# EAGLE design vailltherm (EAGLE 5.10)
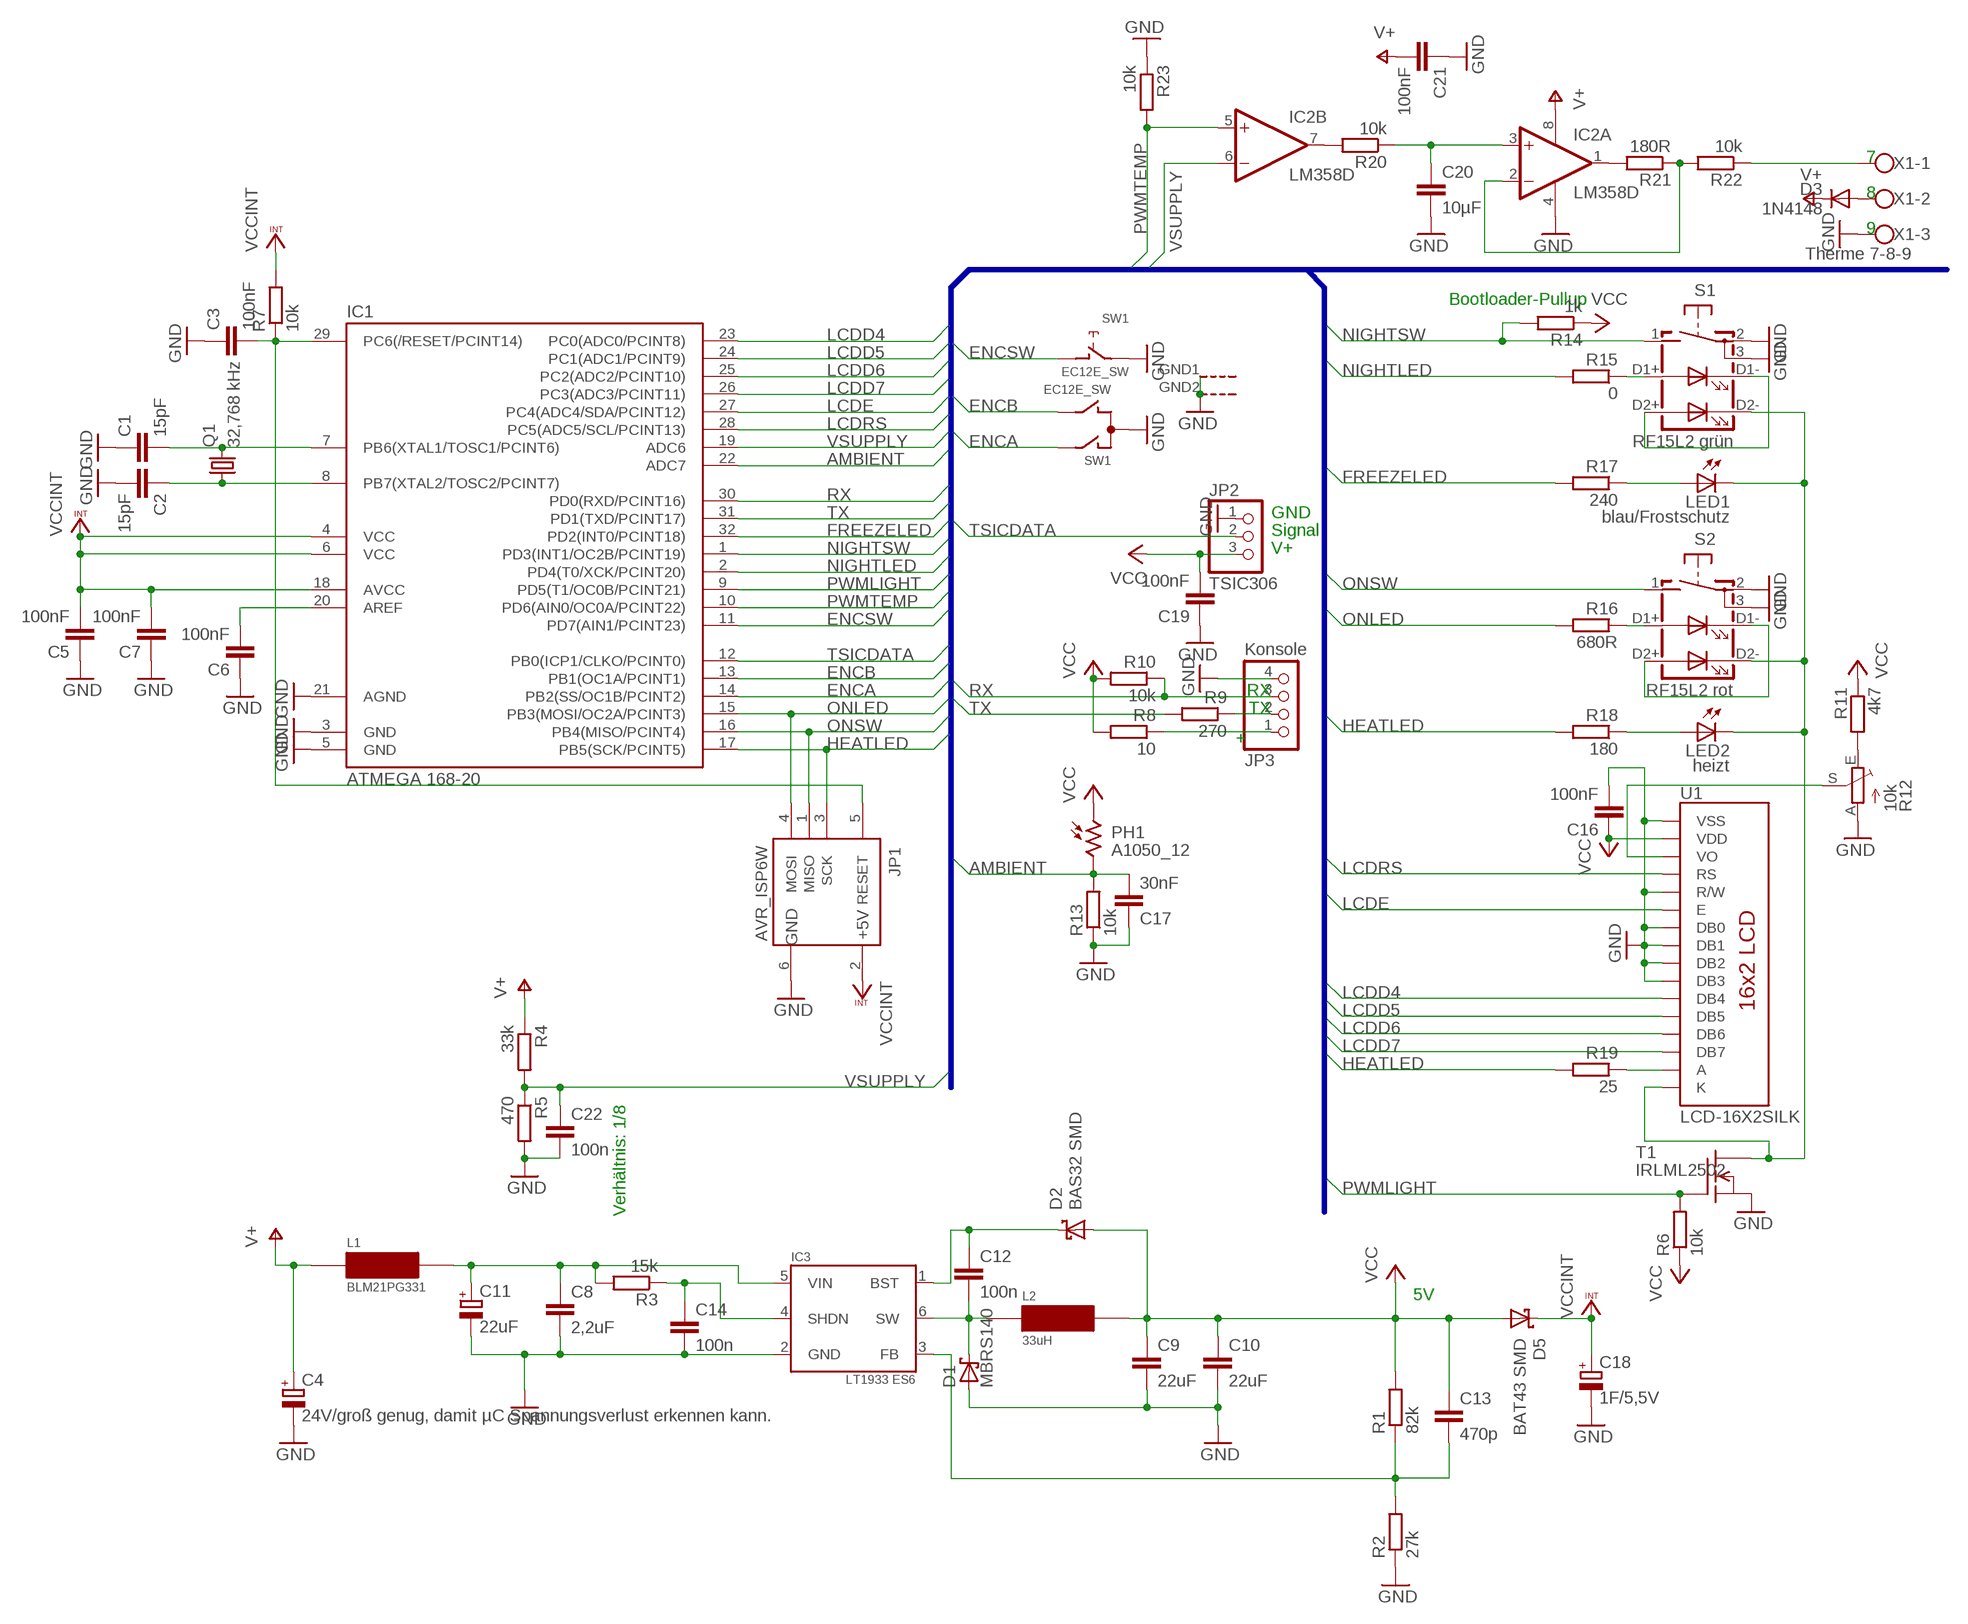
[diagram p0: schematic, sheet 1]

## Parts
C1  15pF  C-EUC0805  [C0805]
C2  15pF  C-EUC0805  [C0805]
C3  100nF  C-EUC0805  [C0805]
C4  24V/groß genug, damit µC Spannungsverlust erkennen kann.  CPOL-EUE5-10.5  [E5-10,5]
C5  100nF  C-EUC0805  [C0805]
C6  100nF  C-EUC0805  [C0805]
C7  100nF  C-EUC0805  [C0805]
C8  2,2uF  C-EUC1206  [C1206]
C9  22uF  C-EUC1206  [C1206]
C10  22uF  C-EUC1206  [C1206]
C11  22uF  CPOL-EUC  [PANASONIC_C]
C12  100n  C-EUC0805  [C0805]
C13  470p  C-EUC0805  [C0805]
C14  100n  C-EUC0805  [C0805]
C16  100nF  C-EUC0805  [C0805]
C17  30nF  C-EUC0805  [C0805]
C18  1F/5,5V  CPOL-EUE5-13  [E5-13]
C19  100nF  C-EUC0805  [C0805]
C20  10µF  C-EUC1206  [C1206]
C21  100nF  C-EUC0805  [C0805]
C22  100n  C-EUC0805  [C0805]
D1  MBRS140  MBRS130LT3  [SMB]
D2  BAS32 SMD  SCHOTTKY-SOD80  [SOD80C]
D3  1N4148  DIODE-MINIMELF  [MINIMELF]
D5  BAT43 SMD  SCHOTTKY-SOD80  [SOD80C]
IC1  ATMEGA 168-20  MEGA48/88/168-AU  [TQFP32-08]
IC2  LM358D  [SO08]
IC3  LT1933 ES6  LT1933S6  [SOT23-6]
JP1  AVR_ISP6W  [WANNE_ML6]
JP2  TSIC306  PINHD-1X3  [1X03]
JP3  Konsole  PINHD-1X4  [1X04]
L1  BLM21PG331  SPULEN-0805  [0805]
L2  33uH  SPULEN-PISG  [L-PISG]
LED1  blau/Frostschutz  LED3MM  [LED3MM]
LED2  heizt  LED3MM  [LED3MM]
PH1  A1050_12  [T0-46-A10XX]
Q1  32,768 kHz  CRYSTALTC38H  [TC38H]
R1  82k  R-EU_R0805  [R0805]
R2  27k  R-EU_R0805  [R0805]
R3  15k  R-EU_R0805  [R0805]
R4  33k  R-EU_R0805  [R0805]
R5  470  R-EU_R0805  [R0805]
R6  10k  R-EU_R0805  [R0805]
R7  10k  R-EU_R0805  [R0805]
R8  10  R-EU_R0805  [R0805]
R9  270  R-EU_R0805  [R0805]
R10  10k  R-EU_R0805  [R0805]
R11  4k7  R-EU_R0805  [R0805]
R12  10k  TRIM_EU-PT10  [PT-10]
R13  10k  R-EU_R0805  [R0805]
R14  1k  R-EU_0207/12  [0207/12]
R15  0  R-EU_R0805  [R0805]
R16  680R  R-EU_R0805  [R0805]
R17  240  R-EU_R0805  [R0805]
R18  180  R-EU_R0805  [R0805]
R19  25  R-EU_R0805  [R0805]
R20  10k  R-EU_R0805  [R0805]
R21  180R  R-EU_R0805  [R0805]
R22  10k  R-EU_R0805  [R0805]
R23  10k  R-EU_R0805  [R0805]
S1  RF15L2 grün  RF15L2  [RF15L2]
S2  RF15L2 rot  RF15L2  [RF15L2]
SW1  EC12E_SW  [ALPS_EC12E_SW]
T1  IRLML2502  N-MOSFET-ENH-SOT23  [SOT23]
U1  LCD-16X2SILK  [LCD-16X2]
X1  Therme 7-8-9  W237-3E  [W237-3E]

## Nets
AMBIENT: C17.2 IC1.22(ADC7) PH1.2 R13.2
ENCA: IC1.14(PB2(SS/OC1B/PCINT2)) SW1.A
ENCB: IC1.13(PB1(OC1A/PCINT1)) SW1.B
ENCSW: IC1.11(PD7(AIN1/PCINT23)) SW1.D
FREEZELED: IC1.32(PD2(INT0/PCINT18)) R17.2
GND: C1.1 C2.2 C3.1 C4.- C5.1 C6.1 C7.1 C8.2 C9.2 C10.2 C11.- C14.2 C16.2 C17.1 C18.- C19.1 C20.2 C21.1 C22.2 D1.A IC1.3(GND) IC1.5(GND) IC1.21(AGND) IC2.4(P:V-) IC3.2(GND) JP1.6(GND) JP2.1 JP3.4 R2.1 R5.2 R12.A R13.1 R23.1 S1.2(P) S1.3(P) S2.2(P) S2.3(P) SW1.C SW1.E SW1.GND1(G) SW1.GND2(G) T1.2(S) U1.1(VSS) U1.5(R/W) U1.7(DB0) U1.8(DB1) U1.9(DB2) U1.10(DB3) X1.3
HEATLED: IC1.17(PB5(SCK/PCINT5)) JP1.3(SCK) R18.2 R19.2
LCDD4: IC1.23(PC0(ADC0/PCINT8)) U1.11(DB4)
LCDD5: IC1.24(PC1(ADC1/PCINT9)) U1.12(DB5)
LCDD6: IC1.25(PC2(ADC2/PCINT10)) U1.13(DB6)
LCDD7: IC1.26(PC3(ADC3/PCINT11)) U1.14(DB7)
LCDE: IC1.27(PC4(ADC4/SDA/PCINT12)) U1.6(E)
LCDRS: IC1.28(PC5(ADC5/SCL/PCINT13)) U1.4(RS)
N$1: C1.2 IC1.7(PB6(XTAL1/TOSC1/PCINT6)) Q1.2
N$2: C2.1 IC1.8(PB7(XTAL2/TOSC2/PCINT7)) Q1.1
N$3: C3.2 IC1.29(PC6(/RESET/PCINT14)) JP1.5(RESET) R7.1
N$7: C14.1 IC3.4(SHDN) R3.1
N$8: C6.2 IC1.20(AREF)
N$9: C12.2 D1.C IC3.6(SW) L2.1
N$10: C8.1 C11.+ IC3.5(VIN) L1.2 R3.2
N$11: C12.1 D2.C IC3.1(BST)
N$12: D3.A X1.2
N$14: IC2.2(A:-IN) R21.1 R22.2
N$15: R11.2 R12.E
N$16: R12.S U1.3(VO)
N$17: LED1.K(C) LED2.K(C) S1.D2-(C2) S2.D2-(C2) T1.3(D) U1.16(K)
N$18: S1.D1-(C1) S1.D2+(A2)
N$19: JP3.2 R9.1
N$20: JP3.1 R8.1
N$22: R15.1 S1.D1+(A1)
N$23: LED1.A R17.1
N$24: C13.2 IC3.3(FB) R1.1 R2.2
N$25: R16.1 S2.D1+(A1)
N$26: LED2.A R18.1
N$27: R19.1 U1.15(A)
N$28: S2.D1-(C1) S2.D2+(A2)
N$30: IC2.1(A:OUT) R21.2
N$31: R22.1 X1.1
N$32: C20.1 IC2.3(A:+IN) R20.1
N$33: IC2.7(B:OUT) R20.2
NIGHTLED: IC1.2(PD4(T0/XCK/PCINT20)) R15.2
NIGHTSW: IC1.1(PD3(INT1/OC2B/PCINT19)) R14.2 S1.1(S)
ONLED: IC1.15(PB3(MOSI/OC2A/PCINT3)) JP1.4(MOSI) R16.2
ONSW: IC1.16(PB4(MISO/PCINT4)) JP1.1(MISO) S2.1(S)
PWMLIGHT: IC1.9(PD5(T1/OC0B/PCINT21)) R6.2 T1.1(G)
PWMTEMP: IC1.10(PD6(AIN0/OC0A/PCINT22)) IC2.5(B:+IN) R23.2
RX: IC1.30(PD0(RXD/PCINT16)) JP3.3 R10.1
TSICDATA: IC1.12(PB0(ICP1/CLKO/PCINT0)) JP2.2
TX: IC1.31(PD1(TXD/PCINT17)) R9.2
V+: C4.+ C21.2 D3.C IC2.8(P:V+) L1.1 R4.1
VCC: C9.1 C10.1 C13.1 C16.1 C19.2 D2.A D5.A JP2.3 L2.2 PH1.1 R1.2 R6.1 R8.2 R10.2 R11.1 R14.1 U1.2(VDD)
VCCINT: C5.2 C7.2 C18.+ D5.C IC1.4(VCC) IC1.6(VCC) IC1.18(AVCC) JP1.2(+5V) R7.2
VSUPPLY: C22.1 IC1.19(ADC6) IC2.6(B:-IN) R4.2 R5.1

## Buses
RX,TX,PWMTEMP,PWMLIGHT,AMBIENT,TSICDATA,TSICPOWER,VSUPPLY,ENCA,ENCB,ENCSW,ONSW,NIGHTSW,ONLED,NIGHTLED,HEATLED,FREEZELED,REMOTE-ON,REMOTE-OFF,LCDD[4..7],LCDRS,LCDE

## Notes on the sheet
- 7
- 8
- 9
- Bootloader-Pullup
- GND
- Signal
- V+
- RX
- TX
- +
- Verhältnis: 1/8
- 5V

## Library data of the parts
C1-C3 C5-C10 C12-C14 C16 C17 C19-C22 = rcl:C-EU: CAPACITOR, European symbol
C4 C11 C18 = rcl:CPOL-EU: POLARIZED CAPACITOR, European symbol
D1 = diode:MBRS130LT3: Schottky Power Rectifier
D2 D5 = 11my-ICs:SCHOTTKY-
D3 = diode:DIODE-: DIODE
IC1 = avr-6:MEGA48/88/168
IC2 = linear:LM358: OP AMP also LM158; LM258; LM2904 Source: http://cache.national.com/ds/LM/LM158.pdf
IC3 = 11my-ICs:LT1933
JP1 = 11my-AVR:AVR_ISP6: ISP (In System Programming) Stecker fr AVRs ber diesen Anschlu kann ein AVR mit einem Standard ISP-Kabel direkt an einen Parallelport des PCs angeschlossen und programmiert werden.
JP2 = pinhead:PINHD-1X3: PIN HEADER
JP3 = pinhead:PINHD-1X4: PIN HEADER
L1 L2 = 11my-RCA:SPULEN: SMD-Power-Induktivitten
LED1 LED2 = led:LED: LED
PH1 = photo-elements:A10: Sensor Robust Light Sensing Applications
Q1 = crystal:CRYSTAL: CRYSTAL
R1-R11 R13-R23 = rcl:R-EU_: RESISTOR, European symbol
R12 = pot:TRIM_EU-: POTENTIOMETER
S1 S2 = switch-misc:RF15L2: RAFI SWITCH
SW1 = switch-alps:EC12E_SW: ALPS rotary Encoder EC12E series with switch
T1 = 11my-ICs:N-MOSFET-ENH-: N-Channel Enhancement MOSFET 50V; 20A; 0,080Ohm
U1 = SparkFun:LCD-16X2
X1 = con-wago-508:W237-3E: WAGO SREW CLAMP

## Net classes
0 default: clearance 0.25 mm

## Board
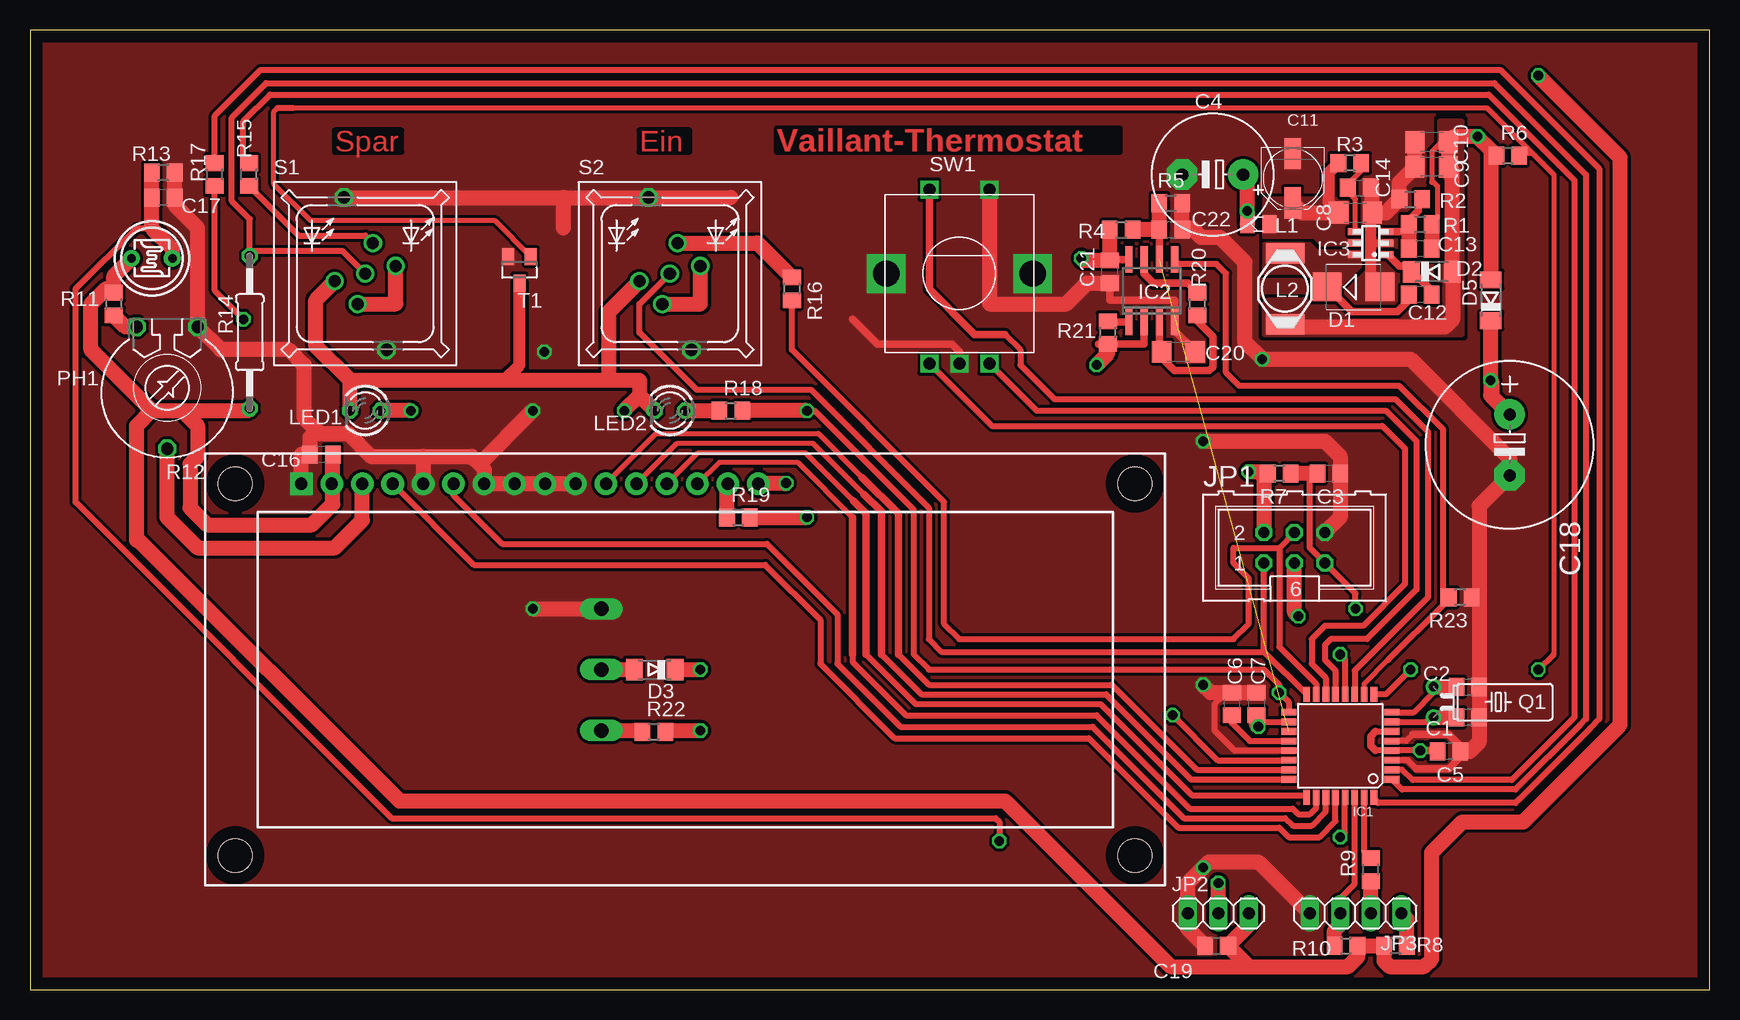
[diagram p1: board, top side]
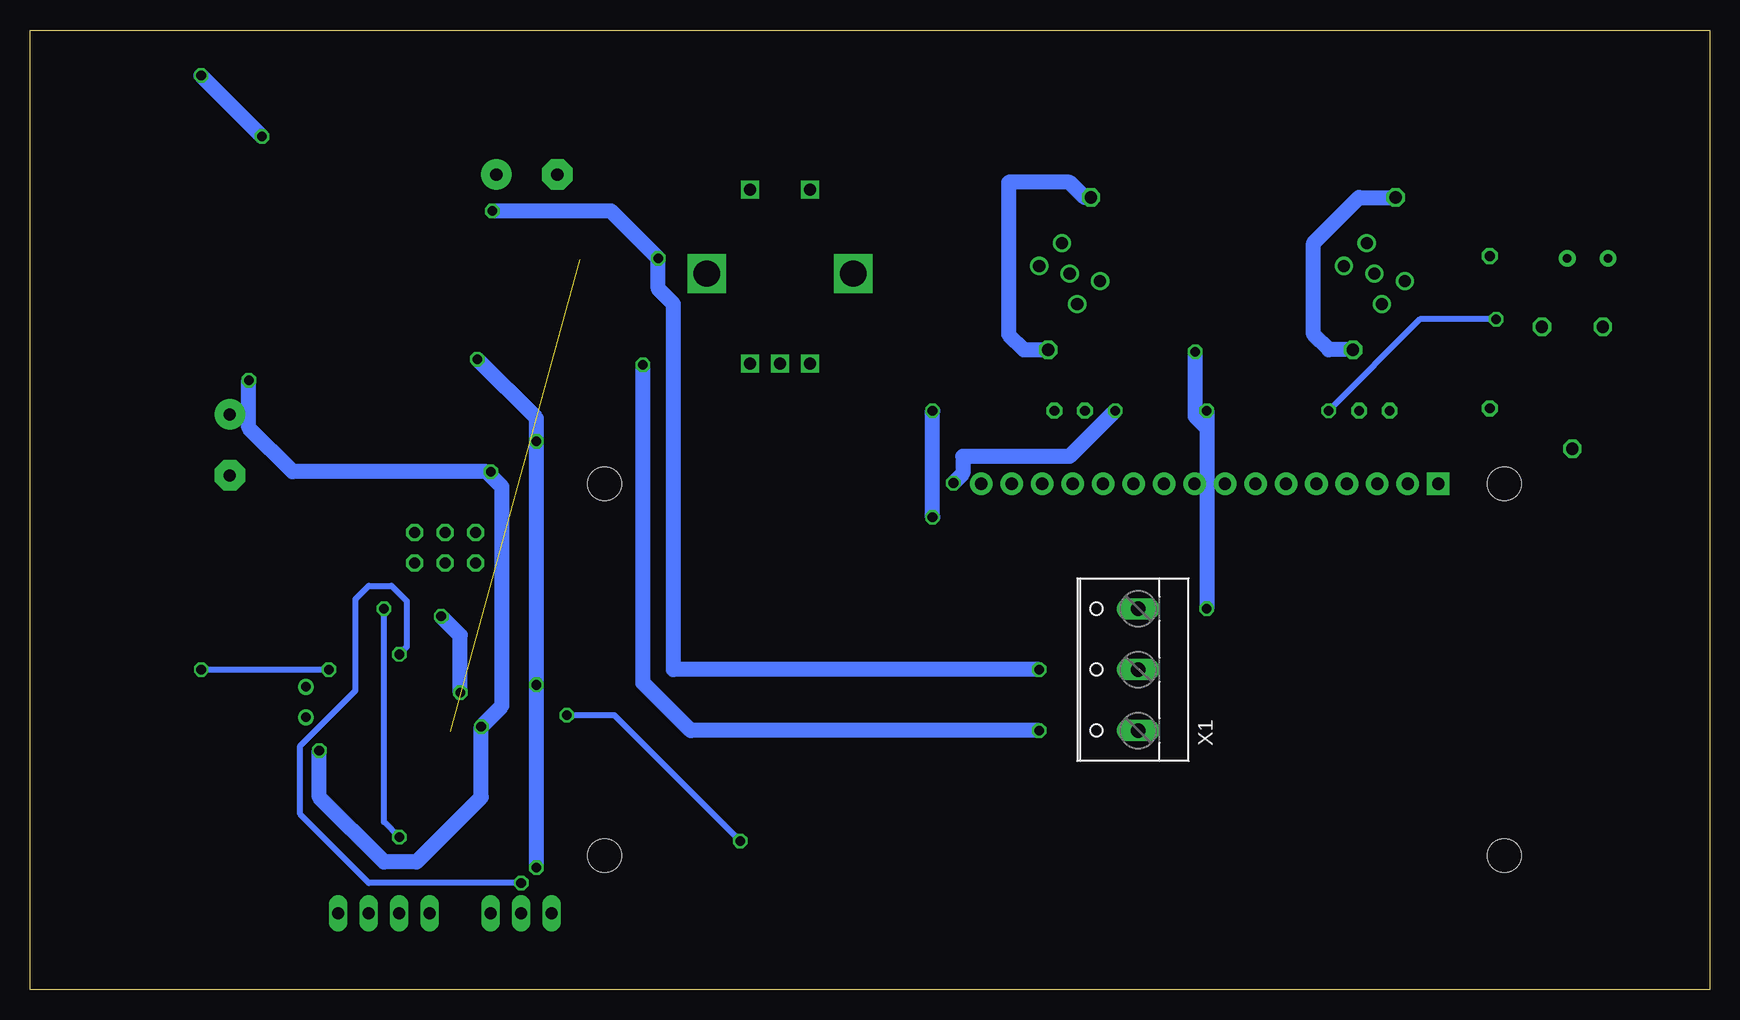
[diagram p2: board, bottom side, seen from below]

Size 140 x 80 mm. Coordinates in mm from the lower left corner, seen from the top.
Outline: 0,0 140,0 140,80 0,80 0,0
Copper layers (1*16): Top 0.035mm / dielectric 1.5mm / Bottom 0.035mm
Design rules "CCCB-Fraese": minimum track width 10mil, minimum drill 0.8mm, track to track 9mil, track to pad 9mil, pad to pad 9mil, via to via 9mil, smd to smd 9mil, copper to edge 40mil, drill to drill 8mil, minimum pad ring 10mil, minimum via ring 8mil, stop-mask expansion 4mil, vias tented up to drill 0mil, thermal gap 10mil
tRestrict: 4 lines

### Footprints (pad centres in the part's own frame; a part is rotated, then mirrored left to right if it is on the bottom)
C0805 = smd 1.3 x 1.5: 1 -0.95,0; 2 0.95,0
E5-10,5 = drill 1.016 pad 2.54 round: + -2.54,0 | drill 1.016 pad 2.54 octagon: - 2.54,0
C1206 = smd 1.6 x 1.8: 1 -1.4,0; 2 1.4,0
PANASONIC_C = smd 2.6 x 1.4: + 2.05,0; - -2.05,0
E5-13 = drill 1.016 pad 2.54 round: + -2.54,0 | drill 1.016 pad 2.54 octagon: - 2.54,0
SMB = smd 2.4 x 2.4: A 2.2,0; C -2.2,0
SOD80C = smd 1.4 x 1.8: A 1.7,0; C -1.7,0
MINIMELF = smd 1.4 x 1.8: A 1.7,0; C -1.7,0
TQFP32-08 = smd 1.27 x 0.559: 1 -4.293,2.8; 2 -4.293,2; 3 -4.293,1.2; 4 -4.293,0.4; 5 -4.293,-0.4; 6 -4.293,-1.2; 7 -4.293,-2; 8 -4.293,-2.8; 17 4.293,-2.8; 18 4.293,-2; 19 4.293,-1.2; 20 4.293,-0.4; 21 4.293,0.4; 22 4.293,1.2; 23 4.293,2; 24 4.293,2.8 | smd 0.559 x 1.27: 9 -2.8,-4.293; 10 -2,-4.293; 11 -1.2,-4.293; 12 -0.4,-4.293; 13 0.4,-4.293; 14 1.2,-4.293; 15 2,-4.293; 16 2.8,-4.293; 25 2.8,4.293; 26 2,4.293; 27 1.2,4.293; 28 0.4,4.293; 29 -0.4,4.293; 30 -1.2,4.293; 31 -2,4.293; 32 -2.8,4.293
SO08 = smd 0.6 x 2.2: 1 -1.905,-2.6; 2 -0.635,-2.6; 3 0.635,-2.6; 4 1.905,-2.6; 5 1.905,2.6; 6 0.635,2.6; 7 -0.635,2.6; 8 -1.905,2.6
SOT23-6 = smd 0.6 x 1.2: 1 -0.95,-1.3; 2 0,-1.3; 3 0.95,-1.3; 4 0.95,1.3; 5 0,1.3; 6 -0.95,1.3
WANNE_ML6 = drill 0.914 octagon: 1 -2.54,-1.27; 2 -2.54,1.27; 3 0,-1.27; 4 0,1.27; 5 2.54,-1.27; 6 2.54,1.27
1X03 = drill 1.016 long: 1 -2.54,0; 2 0,0; 3 2.54,0
1X04 = drill 1.016 long: 1 -3.81,0; 2 -1.27,0; 3 1.27,0; 4 3.81,0
0805 = smd 1.15 x 1.5: 1 -0.925,0; 2 0.925,0
L-PISG = smd 3.2 x 1.7: 1 0,-2.95; 2 0,2.95
LED3MM = drill 0.813 octagon: A -1.27,0; K 1.27,0
T0-46-A10XX = drill 0.7 pad 1.4 round: 1 -1.7,0; 2 1.7,0
TC38H = drill 0.813 round: 1 -1.27,0; 2 1.27,0
R0805 = smd 1.3 x 1.5: 1 -0.95,0; 2 0.95,0
PT-10 = drill 1.016 octagon: A -2.54,-5.08; E 2.54,-5.08; S 0,5.08
0207/12 = drill 0.813 octagon: 1 -6.35,0; 2 6.35,0
RF15L2 = drill 1.016 round: 1 0,0; D1+ 0.635,2.54; D1- 2.54,0.635; D2+ -0.635,-2.54; D2- -2.54,-0.635 | drill 1.016 octagon: 2 -1.778,6.35; 3 1.778,-6.35
ALPS_EC12E_SW = drill 1 square: A -2.5,-7.5; B 2.5,-7.5; C 0,-7.5; D -2.5,7; E 2.5,7 | drill 2.2 square: GND1 -6.1,0; GND2 6.1,0
SOT23 = smd 1 x 1.4: 1 -0.95,-1.1; 2 0.95,-1.1; 3 0,1.1
LCD-16X2 = drill 1.016 pad 1.88 square: 1 -32,15.5 | drill 1.016 pad 1.88 round: 2 -29.46,15.5; 3 -26.92,15.5; 4 -24.38,15.5; 5 -21.84,15.5; 6 -19.3,15.5; 7 -16.76,15.5; 8 -14.22,15.5; 9 -11.68,15.5; 10 -9.14,15.5; 11 -6.6,15.5; 12 -4.06,15.5; 13 -1.52,15.5; 14 1.02,15.5; 15 3.56,15.5; 16 6.1,15.5 | hole 2.8: -37.5,15.5; -37.5,-15.5; 37.5,15.5; 37.5,-15.5
W237-3E = drill 1.194 long: 1 -5.08,-0.635; 2 0,-0.635; 3 5.08,-0.635

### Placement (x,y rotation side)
C1  119.86,22.7 180 top
C2  119.86,25.24 0 top
C3  108.27,43.02 180 top
C4  98.58,67.94 180 top
C5  118.27,19.84 180 top
C6  100.17,23.81 270 top
C7  102.23,23.81 270 top
C8  110.49,64.77 0 top
C9  116.84,68.58 180 top
C10  116.84,70.64 180 top
C11  105.25,67.63 270 top
C12  115.89,57.94 180 top
C13  115.89,61.75 180 top
C14  110.81,66.83 0 top
C16  24.29,44.61 180 top
C17  11.11,66.04 180 top
C18  123.35,45.4 270 top
C19  98.9,3.65 0 top
C20  95.73,53.18 0 top
C21  90.01,59.85 90 top
C22  95.09,63.34 0 top
D1  110.33,58.58 0 top
D2  116.84,59.85 0 top
D3  52.07,26.67 180 top
D5  121.76,57.47 90 top
IC1  109.22,20.32 180 top
IC2  93.5,58.26 0 top
IC3  111.76,62.23 90 top
JP1  105.41,36.83 0 top
JP2  99.06,6.35 0 top
JP3  110.49,6.35 180 top
L1  102.39,63.82 0 top
L2  104.62,58.42 180 top
LED1  27.94,48.26 180 top
LED2  53.34,48.26 180 top
PH1  10.16,60.96 0 top
Q1  117,23.97 270 top
R1  115.89,63.82 0 top
R2  115.09,65.88 0 top
R3  110.01,68.9 180 top
R4  90.96,63.34 0 top
R5  95.09,65.56 0 top
R6  123.19,69.53 0 top
R7  104.14,43.02 180 top
R8  113.82,3.65 180 top
R9  111.76,10 90 top
R10  109.7,3.65 0 top
R11  6.99,57.15 270 top
R12  11.43,50.16 180 top
R13  11.11,68.1 180 top
R14  18.32,54.8 90 top
R15  18.26,67.94 90 top
R16  63.5,58.42 270 top
R17  15.4,67.94 90 top
R18  58.42,48.26 0 top
R19  59.05,39.37 0 top
R20  97.31,57.15 90 top
R21  89.85,54.77 90 top
R22  52,21.5 0 top
R23  119.22,32.7 180 top
S1  27.94,59.69 0 top
S2  53.34,59.69 0 top
SW1  77.47,59.69 0 top
T1  40.8,60.01 180 top
U1  54.61,26.67 0 top
X1  48.26,26.67 90 bottom

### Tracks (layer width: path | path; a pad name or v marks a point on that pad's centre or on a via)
AMBIENT  (via drill 0.8)
  Top 0.5: IC1.22 98.99,19.12 v95.25,22.86 | 10.16,63.5 8.89,63.5 3.81,58.42 3.81,40.64 30.16,14.29 80.49,14.29 80.8,13.97 v80.8,12.38
  Top 1.27: R13.2 C17.2 10.16,63.5 11.86,61.8 PH1.2
  Bottom 0.5: v80.8,12.38 91.28,22.86 v95.25,22.86
ENCA
  Top 0.5: SW1.A 80.17,46.99 112.71,46.99 114.62,45.09 114.62,33.81 111.12,30.32 107.95,30.32 106.84,29.21 106.84,27.15 108.02,25.96 IC1.14
ENCB
  Top 0.5: SW1.B 83.9,48.26 113.03,48.26 115.57,45.72 115.57,33.34 111.44,29.21 108.43,29.21 107.95,28.73 107.95,27.46 108.82,26.59 IC1.13
ENCSW
  Top 0.5: IC1.11 110.42,26.6 116.52,32.7 116.52,46.51 113.82,49.21 85.41,49.21 82.55,52.07 82.55,53.34 81.28,54.61
  Top 0.61: 81.28,54.61 78.74,54.61 74.97,58.38 SW1.D
FREEZELED
  Top 0.5: R17.2 15.4,72.87 19.21,76.68 122.56,76.68 130.81,68.42 130.81,22.54 130.02,21.75 124.14,15.87 123.83,15.56 112.39,15.56 112.02,15.93 IC1.32
GND  (via drill 0.8)
  Top 0.5: IC1.5 114.7,20.72 115.25,21.27 | IC1.3 114.86,19.12 115.57,18.41 | IC1.21 100.41,19.92 98.9,21.43 99.22,21.11 98.74,21.59 98.74,23.81 99.38,24.45 99.86,24.45 C6.1
  Top 0.61: 111.76,62.23 IC3.2 | C20.2 97.13,53.21 95.41,54.93 IC2.4 95.41,57.47 90.01,57.47 C21.1 | 115.25,21.27 118.27,21.27 119.06,20.48 119.06,20 C5.1 119.06,19.69 119.06,19.21 118.27,18.41 115.57,18.41 | SW1.C 77.47,53.18 76.83,53.82 70.64,53.82 68.58,55.88
  Top 0.9: 111.76,64.64 111.76,62.23 111.76,59.69 112.53,58.92
  Top 1.016: 111.76,64.64 C8.2 | D1.A 112.53,58.92
  Top 1.27: C10.2 | C10.2 C9.2 114.14,67.28 R2.1 113.03,64.77 C8.2 111.89,66.7 C14.2 | R5.2 C22.2 96.68,63.34 96.84,63.5 97.63,62.71 99.22,62.71 101.28,60.64 101.28,53.98 v102.71,52.55 115.09,52.55 123.35,44.29 C18.- 120.81,40.32 120.81,32.7 120.81,32.55 C2.2 | 58.42,66.04 S2.2 44.45,66.04 | U1.1 22.61,44.61 C16.2 23.34,46.04 23.65,46.35 24.13,46.35 | S1.2 44.45,66.04 | U1.10 U1.9 U1.8 U1.7 37.85,43.43 37.47,43.81 | C19.1 96.52,5.08 JP2.1 96.52,8.89 v97.79,10.16 98.27,10.64 102.39,10.64 JP3.4 | C2.2 | C2.2 C1.1 120.81,20.64 120.02,19.84 C5.1 | JP1.6 109.22,39.37 C3.1 109.22,43.18 109.22,44.45 107.95,45.72 v97.79,45.72 | 37.47,43.81 36.83,44.45 32.77,44.45 | 24.13,46.35 26.51,46.35 28.42,44.45 32.77,44.45 | 32.77,44.45 U1.5 | C7.1 C6.1 98.43,24.76 v97.79,25.4 | SW1.E 80.05,66.69 80.01,66.65 80.01,57.15 86.36,57.15 88.11,58.9 C21.1 | 44.45,66.04 44.45,63.5 | 37.47,43.81 v41.91,48.26 | R13.1 C17.1 12.06,65.41 13.97,63.5 R12.A | R12.A | R12.A 15.88,53.34 21.59,53.34 22.86,52.07 22.86,47.62 24.13,46.35 | v41.91,31.75 X1.3
  Bottom 1.27: v102.71,52.55 97.79,47.62 v97.79,45.72 v97.79,25.4 v97.79,10.16 | S1.3 31.75,53.34 33.02,54.61 33.02,62.23 29.21,66.04 S1.2 | S2.3 57.15,53.34 58.42,54.61 58.42,67.31 53.34,67.31 52.07,66.04 S2.2 | v41.91,48.26 41.91,46.83 | 41.91,46.83 v41.91,31.75 | 41.91,46.83 42.86,47.78 v42.86,53.18
  pour Top (isolate 0.254, rank 3, no thermals): 102.87,54.61 119.38,54.61 119.38,72.39 102.87,72.39
  pour Top (isolate 0.254, rank 5, no thermals): 0,80.01 0,0 139.7,0 139.7,80.01
  pour Top (isolate 0.254, rank 4, no thermals): 22.86,72.39 101.6,72.39 101.6,68.58 22.86,68.58
  pour Top (isolate 0.1, rank 4, no thermals): 1.27,29.21 13.97,29.21 13.97,25.4 1.27,25.4
HEATLED  (via drill 0.8)
  Top 0.5: v64.77,48.26 65.41,48.26 73.66,40.01 73.66,27.94 74.93,26.67 102.87,26.67 104.14,25.4 v104.14,24.77 104.93,23.98 IC1.17
  Top 1.27: v64.77,48.26 R18.2 | R19.2 v64.77,39.37 | v64.77,39.37 | JP1.3 105.41,31.43 v105.73,31.11
  Bottom 1.27: v64.77,39.37 v64.77,48.26 | v105.73,31.11 104.14,29.53 v104.14,24.77
LCDD4
  Top 0.406: U1.11 52.2,46.35 65.72,46.35 69.37,42.7 69.85,42.23
  Top 0.5: IC1.23 97.25,18.32 90.17,25.4 74.93,25.4 72.39,27.94
  Top 0.61: 72.39,27.94 72.39,39.69 69.37,42.7
LCDD5
  Top 0.406: 69.53,41.27 65.25,45.56 53.94,45.56 U1.12
  Top 0.5: IC1.24 96.78,17.52 89.69,24.61 74.3,24.61 70.96,27.94
  Top 0.61: 70.96,27.94 70.96,39.85 69.53,41.27
LCDD6
  Top 0.406: U1.13 55.69,44.77 64.61,44.77 68.66,40.72 69.06,40.32
  Top 0.5: 69.69,27.94 73.82,23.81 89.22,23.81 96.84,16.19 106.25,16.19 IC1.25
  Top 0.61: 69.69,27.94 69.69,39.69 68.66,40.72
LCDD7
  Top 0.406: 68.58,39.37 63.98,43.97 57.47,43.97 55.66,42.17 U1.14
  Top 0.5: IC1.26 107.22,15.14 106.68,14.61 105.73,14.61 105.25,15.08 96.68,15.08 88.9,22.86 73.03,22.86 68.58,27.3 68.58,27.94
  Top 0.61: 68.58,39.37 68.58,27.94
LCDE
  Top 0.5: IC1.27 108.02,14.83 106.84,13.65 105.25,13.65 104.62,14.29 96.2,14.29 88.58,21.91 72.55,21.91 67.31,27.15 67.31,31.27 61.44,37.15 39.37,37.15 35.31,41.21 U1.6
LCDRS
  Top 0.5: IC1.28 108.82,14.05 107.47,12.7 104.93,12.7 104.14,13.49 95.73,13.49 88.27,20.95 72.07,20.95 65.88,27.15 65.88,30.8 61.28,35.4 37,35.4 U1.4
N$1
  Top 0.5: IC1.7 116.62,22.32 Q1.2
  Top 1.27: Q1.2 C1.2
N$2
  Top 0.5: IC1.8 115.35,23.12 117,24.77 Q1.1
  Top 1.27: Q1.1 C2.1
N$3  (via drill 0.8)
  Top 0.5: JP1.5 106.68,36.83 106.68,42.38 C3.2 | JP1.5 | IC1.29 109.62,13.1 v109.22,12.7 | v110.49,31.75 110.49,33.02 JP1.5
  Top 1.27: C3.2 R7.1 | C3.2
  Bottom 0.5: v109.22,12.7 110.49,13.97 v110.49,31.75
N$7
  Top 0.406: IC3.4 110.49,63.21 110.49,65.88 109.86,66.51 C14.1 109.86,67.15 110.97,68.26 R3.1
N$8
  Top 0.5: 100.09,22.79 C6.2 100.17,22.23 101.68,20.72 IC1.20
N$9
  Top 0.61: C12.2 114.94,57.47 113.98,56.52 110.19,56.52 D1.C
  pour Top (isolate 0.254, no thermals): 102.87,62.23 106.68,62.23 107.31,61.59 110.97,61.59 110.97,60.33 108.11,57.47 107,57.47 107,59.05 106.36,59.69 102.87,59.69
N$10
  Top 1.016: R3.2 108.27,68.1 108.27,65.59 C8.1
  Top 1.27: C8.1 106.06,64.77 C11.+
  pour Top (isolate 0.254, rank 2, no thermals): 110.97,62.07 102.87,62.07 102.87,66.04 110.97,66.04
N$11
  Top 0.61: IC3.1 113.19,61.28 114.14,60.33 114.94,60.33 115.14,60.12 D2.C 115.62,59.37 115.73,59.37 116.84,58.26 C12.1
N$12
  Top 1.27: X1.2 D3.A
N$14  (via drill 0.8)
  Top 0.61: IC2.2 92.87,53.82 R21.1 89.06,53.82
  Top 1.27: v88.9,52.07 89.85,53.02 R21.1 | R22.2 53.04,21.59 v55.88,21.59
  Bottom 1.27: v88.9,52.07 88.9,25.56 84.93,21.59 v55.88,21.59
N$15
  Top 1.27: R11.2 7.94,55.24 R12.E
N$16
  Top 1.27: R12.S 11.43,39.37 13.97,36.83 25.4,36.83 27.69,39.12 U1.3
N$17  (via drill 0.8)
  Top 1.016: 39.53,50.8 40.8,52.07 T1.3
  Top 1.27: LED1.K 26.67,50.8 | 50.8,49.53 50.8,50.8 48.26,50.8 | 50.8,49.53 LED2.K | 26.67,50.8 39.53,50.8 48.26,50.8 | U1.16 62.97,42.17 v63.02,42.23 | 50.8,49.53 v49.53,48.26 | S2.D2- 48.26,56.52 48.26,50.8 | 26.67,50.8 23.81,53.66 23.81,57.47 S1.D2-
  Bottom 1.27: v63.02,42.23 62.23,43.02 62.23,44.45 53.34,44.45 v49.53,48.26
N$18
  Top 1.27: S1.D1- 30.48,57.15 S1.D2+
N$19
  Top 1.27: JP3.2 R9.1 | JP3.2
N$20
  Top 1.27: JP3.1 114.77,5.88 R8.1
N$22
  Top 0.5: R15.1 22.39,62.87 27.94,62.87 S1.D1+
N$23  (via drill 0.8)
  Top 0.5: v17.78,55.88 15.4,58.26 R17.1
  Top 1.27: v31.75,48.26 LED1.A
  Bottom 0.5: v17.78,55.88 24.13,55.88 v31.75,48.26
N$24
  Top 0.61: R2.2 116.04,65.72 115.73,65.41 115.73,64.93 114.94,64.14 R1.1 114.94,63.18 IC3.3
  Top 1.27: R1.1 C13.2
N$25
  Top 1.27: S2.D1+ 60.64,62.23 R16.1
N$26
  Top 1.27: LED2.A R18.1
N$27
  Top 1.27: R19.1 58.1,42.1 U1.15
N$28
  Top 1.27: S2.D2+ 55.88,57.15 S2.D1-
N$30
  Top 0.61: R21.2 89.85,55.66 IC2.1
N$31
  Top 1.27: R22.1 50.96,21.59 X1.1
N$32
  Top 0.61: R20.1 97.31,55.72 98.58,54.45 98.58,51.91 98.27,51.59 95.41,51.59 94.46,52.55 94.46,53.05 C20.1 94.14,53.18 IC2.3
N$33
  Top 0.61: IC2.7 92.87,59.69 93.66,58.9 96.52,58.9 R20.2
NIGHTLED
  Top 0.5: IC1.2 114.39,18.32 115.25,17.46 123.51,17.46 128.75,22.7 128.75,67.47 121.6,74.61 20,74.61 17.78,72.39 17.78,69.37 R15.2
NIGHTSW
  Top 0.5: 114.36,16.67 IC1.1 | 114.36,16.67 123.83,16.67 129.22,22.07 129.7,22.54 129.7,67.94 122.08,75.56 19.68,75.56 16.83,72.71 16.83,65.72 18.32,64.23 R14.2 18.76,61.59 26.04,61.59 S1.1 | 114.36,16.67
ONLED
  Top 0.5: IC1.15 107.22,25.5 104.14,28.57 104.14,36.83 | 104.14,36.83 JP1.4 | R16.2 63.5,53.34 76.2,40.64 76.2,30.48 77.47,29.21 100.33,29.21 101.6,30.48 101.6,34.29 100.33,35.56 100.33,36.83 104.14,36.83
ONSW
  Top 0.5: 102.87,28.16 IC1.16 | 102.87,28.16 JP1.1 | 102.87,28.16 75.98,28.16 74.93,29.21 74.93,40.16 65.09,50.01 55.56,50.01 50.8,54.77 50.8,57.15 S2.1
PWMLIGHT  (via drill 0.8)
  Top 0.406: 127,27.94 127,67.94 125.25,69.69 | 125.25,69.69 121.44,73.5 21.91,73.5 | 20.64,73.5 20.32,73.18 20.32,67.15 23.34,64.14 38.72,64.14 T1.1 | 125.25,69.69 124.62,69.69 124.46,69.53 R6.2
  Top 0.5: 20.64,73.5 21.91,73.5 | v115.09,26.67 113.04,24.61 IC1.9 | 127,27.94 v125.73,26.67
  Bottom 0.5: v125.73,26.67 v115.09,26.67
PWMTEMP
  Top 0.406: IC1.10 111.22,25.5 113.19,27.46 | IC2.5 95.41,60.33
  Top 0.5: 113.19,27.46 117.79,32.07 117.79,32.7 | 117.79,32.7 117.79,46.67 114.14,50.32 100.81,50.32 99.69,51.44 99.69,59.69 98.9,60.48 95.79,60.48 IC2.5 | 117.79,32.7 R23.2
RX
  Top 0.5: IC1.30 110.42,8.82 109.22,7.62 JP3.3
  Top 1.27: R10.1 108.75,4.92 109.22,5.4 JP3.3
TSICDATA  (via drill 0.8)
  Top 0.5: IC1.12 109.62,27.54 v109.22,27.94
  Top 1.27: JP2.2 v99.06,8.89
  Bottom 0.5: v109.22,27.94 108.58,28.57 108.58,32.38 109.86,33.66 111.76,33.66 112.87,32.54 112.87,24.92 117.47,20.32 117.47,14.61 111.76,8.89 v99.06,8.89
TX
  Top 0.5: IC1.31 111.22,11.49 R9.2
V+  (via drill 0.8)
  Top 0.61: C21.2 90.01,60.86 IC2.8
  Top 1.27: 90.01,60.86 R4.1 | D3.C v55.88,26.67 | v87.63,60.96 87.79,60.8 C21.2 | L1.1 v101.47,64.9 101.47,67.6 C4.+
  Bottom 1.27: v55.88,26.67 86.36,26.67 86.36,57.15 87.63,58.42 v87.63,60.96 91.57,64.9 v101.47,64.9
VCC  (via drill 0.8)
  Top 0.406: C10.1 117.63,70.64 116.84,69.85 116.84,67.31 117,67.31 117.32,66.99 117.32,64.3 | 117.32,64.3 R1.2 | 117.32,64.3
  Top 1.27: L2.2 104.84,55.24 117.95,55.24 118.59,55.88 118.59,59.8 D2.A 118.54,68.28 C9.1 C10.1 | C10.1 | R1.2 C13.1 | 25.24,42.17 C16.1 | 25.24,42.17 U1.2 | R8.2 | R8.2 R10.2 110.65,2.7 109.86,1.91 101.6,1.91 | JP2.3 101.6,5.4 C19.2 101.6,1.91 | C10.1 118.72,71.12 v120.65,71.12 121.76,70.01 | v125.73,76.2 132.56,69.37 132.56,22.07 124.46,13.97 119.38,13.97 116.84,11.43 116.84,2.54 116.2,1.91 113.35,1.91 112.87,2.38 R8.2 | 121.76,70.01 D5.A | PH1.1 6.99,59.48 R11.1 6.67,58.42 6.35,58.42 5.08,57.15 5.08,53.34 10.16,48.26 | 25.24,42.17 25.24,40.48 23.5,38.73 14.76,38.73 13.34,40.16 13.34,43.81 13.97,44.45 13.97,46.99 12.7,48.26 | 10.16,48.26 12.7,48.26 | 10.16,48.26 8.89,46.99 8.89,37.62 | 8.89,37.62 8.89,37.47 | 101.6,1.91 95.09,1.91 81.28,15.72 30.8,15.72 8.89,37.62 | 121.76,70.01 R6.1 | R14.1 18.13,48.26 12.7,48.26
  Bottom 1.27: v125.73,76.2 v120.65,71.12
  pour Top (isolate 0.254, rank 2, no thermals): 102.87,57.15 102.87,54.61 119.38,54.61 119.38,72.39 117.47,72.39 117.47,58.74 115.09,56.36 110.17,56.36 109.06,57.47 103.19,57.47
VCCINT  (via drill 0.8)
  Top 0.5: 112.16,19.92 IC1.4 v115.89,19.92 | 112.17,21.52 IC1.6 | IC1.18 102.78,22.32 C7.2
  Top 0.61: 112.16,19.92 111.76,20.32 111.76,21.11 112.17,21.52 | v115.89,19.92 117.24,19.92 C5.2
  Top 1.27: 102.87,42.7 JP1.2 | 102.87,42.7 R7.2 | 102.87,42.7 102.39,43.18 v101.6,43.18 | v121.76,50.8 121.76,49.53 121.84,49.45 | v121.76,50.8 D5.C | 121.84,49.45 C18.+ 123.51,47.94 | v121.76,50.8 121.84,50.72 121.84,49.45 | C7.2 102.23,22.07 v102.39,21.91
  Bottom 1.27: 101.92,43.18 v101.6,43.18 | 101.92,43.18 118.11,43.18 121.76,46.83 v121.76,50.8 | v115.89,19.92 115.89,16.04 110.49,10.64 107.79,10.64 102.39,16.03 v102.39,21.91 100.65,23.65 100.65,41.91 101.92,43.18
VSUPPLY  (1 unrouted)
  Top 0.61: IC2.6 C22.1
  Top 1.27: R4.2 C22.1 R5.1

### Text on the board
Top: Spar | Ein | Vaillant-Thermostat
tRestrict: DS 2012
